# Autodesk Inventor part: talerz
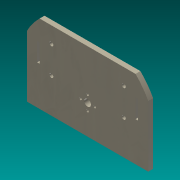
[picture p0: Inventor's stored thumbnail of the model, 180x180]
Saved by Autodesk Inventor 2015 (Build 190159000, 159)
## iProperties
Created: 2016-02
Part Number: talerz
Material: Generic
Document SubType Name: Modeling
Designer: Rafał
Density: 1 g/cm^3
Appearance: Light Beige
Author: Rafał
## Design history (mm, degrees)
sketch "Sketch1" dims "d1" = 14.5
  geometry: C1 r 70 at (0, 0); C2 r 1.25 at (0, 7.25); C3 r 1.25 at (-7.25, 0); C4 r 1.25 at (0, -7.25); C5 r 1.25 at (7.25, 0); 2 further points
  constraints: 5 centre point, 2 coincident, 1 vertical alignment, 11 other
  dimensions: "d0" = 140 diameter of C1; "d2" = 2.5 diameter of C2; "d5" = 360 deg dimension on point (0, 0) C2.centre (derived)
extrude "Extrusion1" new body sketch "Sketch1" distance "d7" = 5; taper "d8" = 0 deg
sketch "Sketch3"
  geometry: L1 (0, 0)-(0, 55); L2 (0, 55)-(43.301, 55); L3 (-43.301, 55)-(0, 55); A1 r 70 centre (0, 0) between (43.301, 55) and (-43.301, 55) reference
  constraints: 6 end point, 2 point on circle, 1 collinear, 1 perpendicular, 1 point on line, 1 vertical
  dimensions: "d11" = 55 distance of L1.start L1.end
extrude "Extrusion3" cut sketch "Sketch3" distance "d12" = 7; taper "d13" = 0 deg
sketch "Sketch4"
  geometry: L1 (43.301, 55)-(-43.301, 55) reference; L2 (0, 55)-(0, -66.946); L3 (51.5, -29)-(49, -29); L4 (49, -29)-(49, -10); L5 (49, -10)-(51.5, -10); L6 (51.5, -10)-(51.5, -29); L7 (0, 0)-(35.886, 0); L8 (51.5, -19.5)-(49, -19.5); L9 (-51.5, -10)-(-51.5, -29); L10 (-51.5, -29)-(-49, -29); L11 (-49, -29)-(-49, -10); L12 (-49, -10)-(-51.5, -10); L13 (0, 0)-(62, 0); L14 (62, 0)-(62, -32.496); L15 (62, 0)-(62, 32.496); L16 (-62, 0)-(-62, -32.496); L17 (-62, 0)-(-62, 32.496); L18 (62, -32.496)-(73.129, -32.496); L19 (73.129, -32.496)-(73.129, 32.496); L20 (73.129, 32.496)-(62, 32.496); L21 (62, 32.496)-(62, -32.496); L22 (-62, -32.496)-(-82.465, -32.496); L23 (-82.465, -32.496)-(-82.465, 35.893); L24 (-82.465, 35.893)-(-62, 35.893); L25 (-62, 35.893)-(-62, -32.496); C1 r 2 at (37, -33.5); C2 r 2 at (37, -5.5); C3 r 2 at (-37, -33.5); C4 r 2 at (-37, -5.5); A1 r 70 centre (0, 0) between (-43.301, 55) and (43.301, 55) reference; 1 further point
  constraints: 48 end point, 10 symmetric about line, 6 parallel, 5 horizontal, 5 perpendicular, 4 centre point, 3 midpoint, 2 point on circle, 2 point on line, 1 vertical, 3 other
  dimensions: "d14" = 2.5 distance of L4.end L5.end; "d15" = 19 distance of L3.end L4.end; "d16" = 49 distance between parallel lines of L2 L4; "d17" = 10 distance between parallel lines of L7 L5; "d18" = 4 diameter of C1; "d19" = 12 distance from line of C1.centre L4; "d20" = 4.5 distance from line of L3 C1.centre; "d23" = 4.5 distance from line of L5 C2.centre; "d24" = 62 distance of L7.start L13.end
extrude "Extrusion5" cut sketch "Sketch4" distance "d25" = 7; taper "d26" = 0 deg
sketch "Sketch6"
  geometry: L1 (0, 0)-(-21.864, 0); L2 (-21.864, 0)-(-21.864, 30); L3 (-21.864, 30)-(0, 30); L4 (0, 30)-(0, 0); L5 (0, 30)-(110.924, 30); L6 (110.924, 30)-(110.924, 74.677); L7 (110.924, 74.677)-(0, 74.677); L8 (0, 74.677)-(0, 30); L9 (0, 30)-(-83.451, 30); L10 (-83.451, 30)-(-83.451, 74.677); L11 (-83.451, 74.677)-(0, 74.677); L12 (0, 74.677)-(0, 30); L13 (0, 0)-(55.462, 0); L14 (55.462, 0)-(55.462, -50); L15 (55.462, -50)-(0, -50); L16 (0, -50)-(0, 0); L17 (0, -50)-(61.243, -50); L18 (61.243, -50)-(61.243, -72.003); L19 (61.243, -72.003)-(0, -72.003); L20 (0, -72.003)-(0, -50); L21 (0, -50)-(-67.424, -50); L22 (-67.424, -50)-(-67.424, -72.003); L23 (-67.424, -72.003)-(0, -72.003); L24 (0, -72.003)-(0, -50)
  constraints: 48 end point, 12 parallel, 6 horizontal, 6 perpendicular, 2 point on line
  dimensions: "d27" = 30 distance of L1.end L2.end; "d28" = 50 distance of L13.end L14.end
extrude "Extrusion6" cut sketch "Sketch6" distance "d29" = 10; taper "d30" = 0 deg
sketch "Sketch8"
  geometry: C1 r 3.5 at (0, 0); 1 further point
  constraints: 1 centre point, 1 coincident
  dimensions: "d33" = 7 diameter of C1
extrude "Extrusion7" cut sketch "Sketch8" distance "d34" = 10; taper "d35" = 0 deg
body "Solid1"
